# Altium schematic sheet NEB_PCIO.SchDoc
size A4; Organization: Altium Limited; Address1: L3, 12a Rodborough Rd; Address2: Frenchs Forest; Address3: NSW; Address4: Australia 2086; DocumentNumber: 9; SheetNumber: 9; SheetTotal: 10
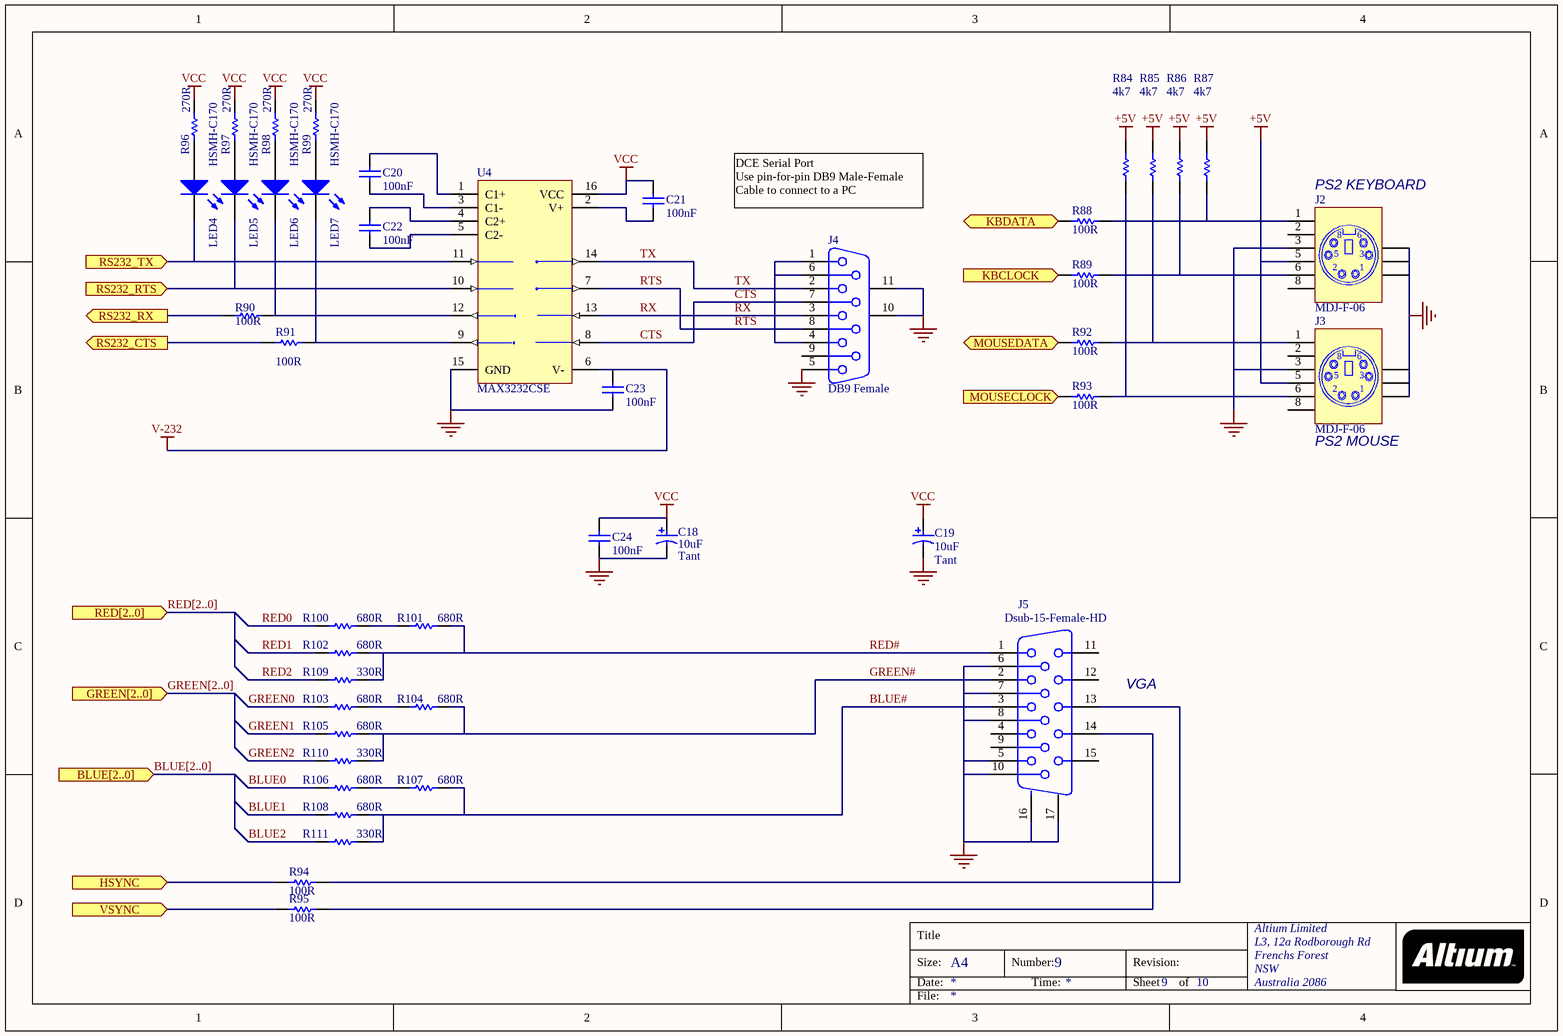
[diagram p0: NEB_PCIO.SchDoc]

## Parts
C18  10uF  Capacitor Type: Tant  [MCCT-B]
C19  10uF  Capacitor Type: Tant  [MCCT-B]
C20  100nF  [CC2012-0805]
C21  100nF  [CC2012-0805]
C22  100nF  [CC2012-0805]
C23  100nF  [CC2012-0805]
C24  100nF  [CC2012-0805]
J2  MDJ-F-06  [MDJ-F-06]
J3  MDJ-F-06  [MDJ-F-06]
J4  DB9 Female  [DSUB1.385-2H9]
J5  Dsub-15-Female-HD  [DB15-VGA-Female]
LED4  HSMH-C170  [SMD _LED]
LED5  HSMH-C170  [SMD _LED]
LED6  HSMH-C170  [SMD _LED]
LED7  HSMH-C170  [SMD _LED]
R84  4k7  [CR2012-0805]
R85  4k7  [CR2012-0805]
R86  4k7  [CR2012-0805]
R87  4k7  [CR2012-0805]
R88  100R  [CR2012-0805]
R89  100R  [CR2012-0805]
R90  100R  [CR2012-0805]
R91  100R  [CR2012-0805]
R92  100R  [CR2012-0805]
R93  100R  [CR2012-0805]
R94  100R  [CR2012-0805]
R95  100R  [CR2012-0805]
R96  270R  [CR2012-0805]
R97  270R  [CR2012-0805]
R98  270R  [CR2012-0805]
R99  270R  [CR2012-0805]
R100  680R  [CR2012-0805]
R101  680R  [CR2012-0805]
R102  680R  [CR2012-0805]
R103  680R  [CR2012-0805]
R104  680R  [CR2012-0805]
R105  680R  [CR2012-0805]
R106  680R  [CR2012-0805]
R107  680R  [CR2012-0805]
R108  680R  [CR2012-0805]
R109  330R  [CR2012-0805]
R110  330R  [CR2012-0805]
R111  330R  [CR2012-0805]
U4  MAX3232CSE  [TSSO5x6-G16]

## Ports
BLUE[2..0] (in), GREEN[2..0] (in), HSYNC (in), KBCLOCK (in), KBDATA (bidir), MOUSECLOCK (in), MOUSEDATA (bidir), RED[2..0] (in), RS232_CTS (out), RS232_RTS (in), RS232_RX (out), RS232_TX (in), VSYNC (in)

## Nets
+5V: J2.5 J3.5 R84.1 R85.1 R86.1 R87.1
GND: C18.2 C19.2 C23.2 C24.2 J2.3 J2.MH1 J2.MH2 J2.MH3 J3.3 J3.MH1 J3.MH2 J3.MH3 J4.5 J4.10(MH1) J4.11(MH2) J5.5 J5.6 J5.7 J5.8 J5.10 J5.16(MH1) J5.17(MH2) U4.15(GND)
V-232: C23.1 U4.6(V-)
VCC: C18.1 C19.1 C21.1 C24.1 R96.2 R97.2 R98.2 R99.2 U4.16(VCC)
BLUE0: R106.1
BLUE1: R108.1
BLUE2: R111.1
BLUE#: J5.3 R107.2 R108.2 R111.2
CTS: J4.7 U4.8(R2IN)
GREEN0: R103.1
GREEN1: R105.1
GREEN2: R110.1
GREEN#: J5.2 R104.2 R105.2 R110.2
HSYNC: R94.1 ; port HSYNC
KBCLOCK: R89.1 ; port KBCLOCK
KBDATA: R88.1 ; port KBDATA
MOUSECLOCK: R93.1 ; port MOUSECLOCK
MOUSEDATA: R92.1 ; port MOUSEDATA
RED0: R100.1
RED1: R102.1
RED2: R109.1
RED#: J5.1 R101.2 R102.2 R109.2
RS232_CTS: R91.1 ; port RS232_CTS
RS232_RTS: LED5.2(K) U4.10(T2IN) ; port RS232_RTS
RS232_RX: R90.1 ; port RS232_RX
RS232_TX: LED4.2(K) U4.11(T1IN) ; port RS232_TX
RTS: J4.8 U4.7(T2OUT)
RX: J4.3 U4.13(R1IN)
TX: J4.2 U4.14(T1OUT)
VSYNC: R95.1 ; port VSYNC
NetC20_1: C20.1 U4.1(C1+)
NetC20_2: C20.2 U4.3(C1-)
NetC21_2: C21.2 U4.2(V+)
NetC22_1: C22.1 U4.4(C2+)
NetC22_2: C22.2 U4.5(C2-)
NetJ2_1: J2.1 R87.2 R88.2
NetJ2_6: J2.6 R86.2 R89.2
NetJ3_1: J3.1 R85.2 R92.2
NetJ3_6: J3.6 R84.2 R93.2
NetJ4_1: J4.1 J4.4 J4.6
NetJ5_13: J5.13 R94.2
NetJ5_14: J5.14 R95.2
NetLED4_1: LED4.1(A) R96.1
NetLED5_1: LED5.1(A) R97.1
NetLED6_1: LED6.1(A) R98.1
NetLED6_2: LED6.2(K) R90.2 U4.12(R1OUT)
NetLED7_1: LED7.1(A) R99.1
NetLED7_2: LED7.2(K) R91.2 U4.9(R2OUT)
NetR100_2: R100.2 R101.1
NetR103_2: R103.2 R104.1
NetR106_2: R106.2 R107.1

Not connected (* = marked no-connect by the designer): J2 2 8; J3 2 8; J4 9; J5 4 9 11 12 15

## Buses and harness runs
bus BLUE[2..0] = port BLUE[2..0]
bus GREEN[2..0] = port GREEN[2..0]
bus RED[2..0] = port RED[2..0]

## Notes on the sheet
- DCE Serial Port
  Use pin-for-pin DB9 Male-Female
  Cable to connect to a PC
- (near J2) PS2 KEYBOARD
- (near J3) PS2 MOUSE
- VGA

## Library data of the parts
C18 C19 = CAP_POLAR: Polar Capacitor; Fitted: True
C20-C24 = CAP: Capacitor; Fitted: True
J2 J3 = MDJ-F-06: Circular DIN, 6 Postion, Jack, Pitch 2.1/2.6 mm; PCB Layout: Complies with manufacturer's recommendation.; Drill Size: Corresponds to nominal value.
J4 = D Connector 9: Receptacle Assembly, 9 Position, Right Angle; Manufacturer: Generic Components; Package Information: Latest Revision: O; Positions: 9; Fitted: True
J5 = Dsub-15-Female-HD: Dsub-15 High density VGA Female connetor; Manufacturer: Generic Components; Package Information: Latest Revision: E; Class I: Connector; Positions: 30; Gender: Receptacle Header; Fitted: True
LED4-LED7 = HSMX-C670: Typical RED GaAs SMD LED Agilent make; Manufacturer: Generic Components; Class I: Optoelectronic; Fitted: True
R84-R111 = RES: Resistor; Fitted: True
U4 = MAX3232EUE: 3.0V TO 5.5V, Low-Power, up to 1Mbps, True RS-232 Transceiver Using Four 0.1µF External Capacitor; Manufacturer: Maxim,ST; Package Information: Latest Revision: 21-0066 C; Class I: Communication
